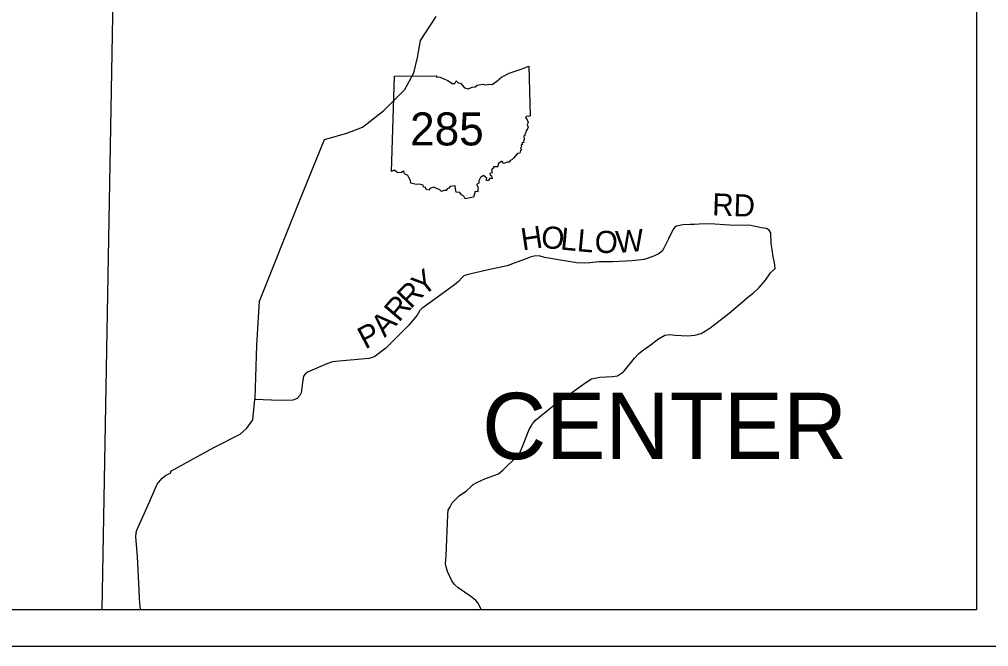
# Model space of a CAD drawing. Extents: x 0 to 34, y 0 to 22.
# Drawn here: x 28.244 to 30.728, y 9.524 to 11.131 of the extents above; entities that cross this region are included whole.
import ezdxf

# ---------------------------------------------------------------- set-up
doc = ezdxf.new("R2010")
doc.units = 0
for name, color, linetype in [('Default', 7, 'Continuous'), ('GM_X_County_Road_Text', 7, 'Continuous'), ('GM_X_State_Route', 7, 'Continuous'), ('GM_X_Township', 7, 'Continuous'), ('GM_X_Township_Text', 7, 'Continuous')]:
    doc.layers.add(name, color=color, linetype=linetype)

msp = doc.modelspace()

# ---------------------------------------------------------------- linework, layer by layer
at = {"layer": 'Default'}
for p, q in [((30.697, 20.4625), (30.697, 9.6182)), ((29.1981, 10.7415), (29.2059, 10.9855)), ((30.697, 9.6182), (19.8526, 9.6182))]:
    msp.add_line(p, q, dxfattribs=at)
msp.add_lwpolyline([(19.7581, 20.557), (30.7915, 20.557), (30.7915, 9.5237), (19.7581, 9.5237)], close=True, dxfattribs=at)
for points in [[(29.2059, 10.9855), (29.3141, 10.9871), (29.3125, 10.9841), (29.3226, 10.9835), (29.3335, 10.9783), (29.3427, 10.975), (29.3538, 10.9673), (29.3606, 10.9674), (29.3634, 10.9738), (29.3685, 10.9688), (29.3747, 10.9679), (29.3852, 10.9562), (29.394, 10.9537), (29.4044, 10.9578), (29.4121, 10.9584), (29.4178, 10.9624), (29.4327, 10.9657), (29.4369, 10.9637), (29.4447, 10.9642), (29.4487, 10.9656), (29.4556, 10.9643), (29.4675, 10.9732), (29.48, 10.9836), (29.4991, 10.9935), (29.5276, 11.0028), (29.5502, 11.0112), (29.5535, 10.8845)], [(29.5535, 10.8845), (29.5502, 10.8828), (29.545, 10.8836), (29.5415, 10.8801), (29.5458, 10.8742), (29.5478, 10.8679), (29.546, 10.861), (29.5478, 10.8553), (29.5466, 10.8505), (29.5434, 10.8458), (29.5422, 10.8413), (29.5395, 10.8365), (29.5397, 10.8338), (29.5371, 10.8318), (29.5375, 10.8238), (29.5362, 10.8194), (29.5367, 10.8157), (29.5323, 10.8147), (29.5333, 10.8115), (29.5306, 10.8091), (29.5312, 10.8049), (29.5281, 10.8023), (29.5311, 10.797), (29.5287, 10.7953), (29.5267, 10.7888), (29.5212, 10.7875), (29.5102, 10.7757), (29.5063, 10.7712), (29.502, 10.7701), (29.4995, 10.7655), (29.4942, 10.7655), (29.486, 10.7623), (29.4808, 10.7678), (29.4716, 10.7612), (29.4705, 10.7536), (29.459, 10.7538), (29.4594, 10.75), (29.4568, 10.7489), (29.4544, 10.745), (29.4558, 10.7382), (29.4503, 10.7364), (29.451, 10.7325), (29.4545, 10.7301), (29.456, 10.7225), (29.4502, 10.724), (29.4455, 10.7176), (29.4406, 10.7191), (29.4422, 10.7245), (29.4339, 10.7311), (29.4262, 10.7258), (29.4221, 10.7175), (29.422, 10.7118), (29.4162, 10.7084), (29.42, 10.7005), (29.4192, 10.695), (29.4194, 10.6898), (29.4121, 10.69), (29.4077, 10.676)], [(29.4077, 10.676), (29.3951, 10.6733), (29.3864, 10.6718), (29.3832, 10.6781), (29.377, 10.6815), (29.3729, 10.6878), (29.3639, 10.6887), (29.3618, 10.6975), (29.3608, 10.7046), (29.3485, 10.7029), (29.3451, 10.6985), (29.3407, 10.6974), (29.3382, 10.6929), (29.3322, 10.6926), (29.3258, 10.6905), (29.3216, 10.6948), (29.3112, 10.6992), (29.3065, 10.7014), (29.2966, 10.698), (29.2946, 10.6938), (29.2868, 10.6956), (29.2849, 10.7002), (29.2802, 10.7016), (29.2791, 10.7065), (29.269, 10.7091), (29.2612, 10.708), (29.2476, 10.7119), (29.2467, 10.7183), (29.2421, 10.7261), (29.2397, 10.7315), (29.2311, 10.7356), (29.2293, 10.7421), (29.2266, 10.7419), (29.224, 10.7393), (29.2144, 10.7381), (29.2106, 10.7407), (29.2052, 10.7452), (29.1981, 10.7415)], [(29.4286, 9.6182), (29.4189, 9.6356), (29.414, 9.642), (29.4011, 9.6522), (29.3689, 9.6742), (29.3591, 9.6829), (29.3523, 9.6923), (29.3413, 9.7162), (29.3379, 9.7283), (29.3367, 9.7355), (29.3379, 9.7563), (29.3427, 9.862), (29.3435, 9.873), (29.3484, 9.8821), (29.3533, 9.8918), (29.3609, 9.8997), (29.3711, 9.9099), (29.3903, 9.923), (29.4014, 9.9329), (29.4075, 9.9396), (29.4168, 9.9445), (29.4392, 9.9544), (29.4721, 9.9667), (29.4835, 9.9763), (29.5187, 10.0106), (29.5257, 10.0185), (29.5335, 10.0362), (29.5511, 10.0798), (29.5557, 10.0889), (29.5591, 10.0946), (29.5667, 10.1038), (29.6124, 10.141), (29.6963, 10.201), (29.7108, 10.2097), (29.7321, 10.2144), (29.7641, 10.2159), (29.7772, 10.2179), (29.7921, 10.2284), (29.8209, 10.2633), (29.8317, 10.275), (29.8436, 10.2846), (29.857, 10.2936), (29.882, 10.3125), (29.8986, 10.3218), (29.9108, 10.3236), (29.9245, 10.3221), (29.9566, 10.3207), (29.9749, 10.3221), (29.9912, 10.3265), (30.0136, 10.3396), (30.0631, 10.3786), (30.097, 10.4073), (30.1114, 10.4196), (30.1249, 10.4298), (30.1403, 10.4446), (30.156, 10.4629), (30.1688, 10.482), (30.1811, 10.4927), (30.1796, 10.5083), (30.1762, 10.5226), (30.173, 10.5413), (30.1711, 10.5572), (30.1697, 10.5844), (30.166, 10.5913), (30.1591, 10.5958), (30.1449, 10.5973), (30.1191, 10.6033), (30.0637, 10.6042), (30.0137, 10.6076), (29.9865, 10.6064), (29.9736, 10.6053), (29.9634, 10.606), (29.9445, 10.6045), (29.9282, 10.6015), (29.924, 10.5984), (29.9191, 10.5924), (29.9074, 10.5685), (29.8949, 10.5435), (29.8911, 10.5371), (29.8809, 10.5299), (29.8673, 10.5238), (29.845, 10.5162), (29.8143, 10.5128), (29.764, 10.5098), (29.7405, 10.5097), (29.7303, 10.5097), (29.7061, 10.5075), (29.6917, 10.5063), (29.6721, 10.5071), (29.5899, 10.5211), (29.5763, 10.5252), (29.5638, 10.5241), (29.5536, 10.5222), (29.5434, 10.518), (29.5188, 10.5089), (29.4942, 10.4994), (29.4424, 10.4884), (29.3913, 10.4763), (29.3837, 10.474), (29.3784, 10.4691), (29.3693, 10.4596), (29.3591, 10.4509), (29.3274, 10.4278), (29.2816, 10.3944), (29.2755, 10.3903), (29.271, 10.385), (29.2638, 10.3736), (29.2426, 10.3475), (29.2086, 10.3134), (29.1836, 10.2887), (29.1552, 10.2671), (29.1492, 10.2645), (29.1397, 10.2622), (29.0542, 10.2546), (29.047, 10.2535), (29.0326, 10.2489), (28.9831, 10.2269), (28.9766, 10.222), (28.9725, 10.2171), (28.9698, 10.2004), (28.9665, 10.1739), (28.9634, 10.1675), (28.9559, 10.1599), (28.9453, 10.1554), (28.9301, 10.1542), (28.8908, 10.1553), (28.8482, 10.1572)]]:
    msp.add_lwpolyline(points, dxfattribs=at)
at = {"layer": 'GM_X_State_Route'}
msp.add_lwpolyline([(28.5552, 9.6182), (28.5525, 9.646), (28.5515, 9.6691), (28.5475, 9.7542), (28.5425, 9.806), (28.5446, 9.8204), (28.5716, 9.8813), (28.5975, 9.9401), (28.6102, 9.9553), (28.6185, 9.9625), (28.6323, 9.9689), (28.6322, 9.9732), (28.743, 10.0339), (28.8104, 10.0679), (28.8276, 10.0834), (28.8424, 10.1052), (28.8482, 10.1572), (28.8484, 10.1595), (28.8528, 10.2967), (28.8598, 10.409), (28.9617, 10.6634), (29.0267, 10.8232), (29.0837, 10.84), (29.124, 10.855), (29.1787, 10.8975), (29.2321, 10.9518), (29.2549, 10.9946), (29.2646, 11.0334), (29.2726, 11.0771), (29.3123, 11.1384)], dxfattribs=at)
at = {"layer": 'GM_X_Township'}
msp.add_line((28.5367, 14.1959), (28.456, 9.6182), dxfattribs=at)

# ---------------------------------------------------------------- texts
at = {"layer": 'Default'}
msp.add_text('285', height=0.08462, dxfattribs=at).set_placement((29.2456, 10.8083))
at = {"layer": 'GM_X_County_Road_Text'}
for s, rotation, p in [('RD', 358.0243, (30.019, 10.6291)), ('H', 8.5191, (29.5339, 10.5389)), ('O', 354.8643, (29.5797, 10.5462)), ('L', 354.4459, (29.6293, 10.5417)), ('L', 354.6233, (29.6717, 10.5376)), ('O', 358.5718, (29.7182, 10.5334)), ('W', 4.7606, (29.7748, 10.5323)), ('Y', 38.1085, (29.2781, 10.4196)), ('R', 45.5023, (29.2469, 10.3877)), ('R', 49.2975, (29.2172, 10.3531)), ('A', 46.3399, (29.1807, 10.3146)), ('P', 27.6658, (29.1307, 10.2848))]:
    msp.add_text(s, height=0.0567, rotation=rotation, dxfattribs=at).set_placement(p)
at = {"layer": 'GM_X_Township_Text'}
msp.add_text('CENTER', height=0.1701, rotation=0, dxfattribs=at).set_placement((29.4301, 10.0042))

doc.saveas('drawing.dxf')
